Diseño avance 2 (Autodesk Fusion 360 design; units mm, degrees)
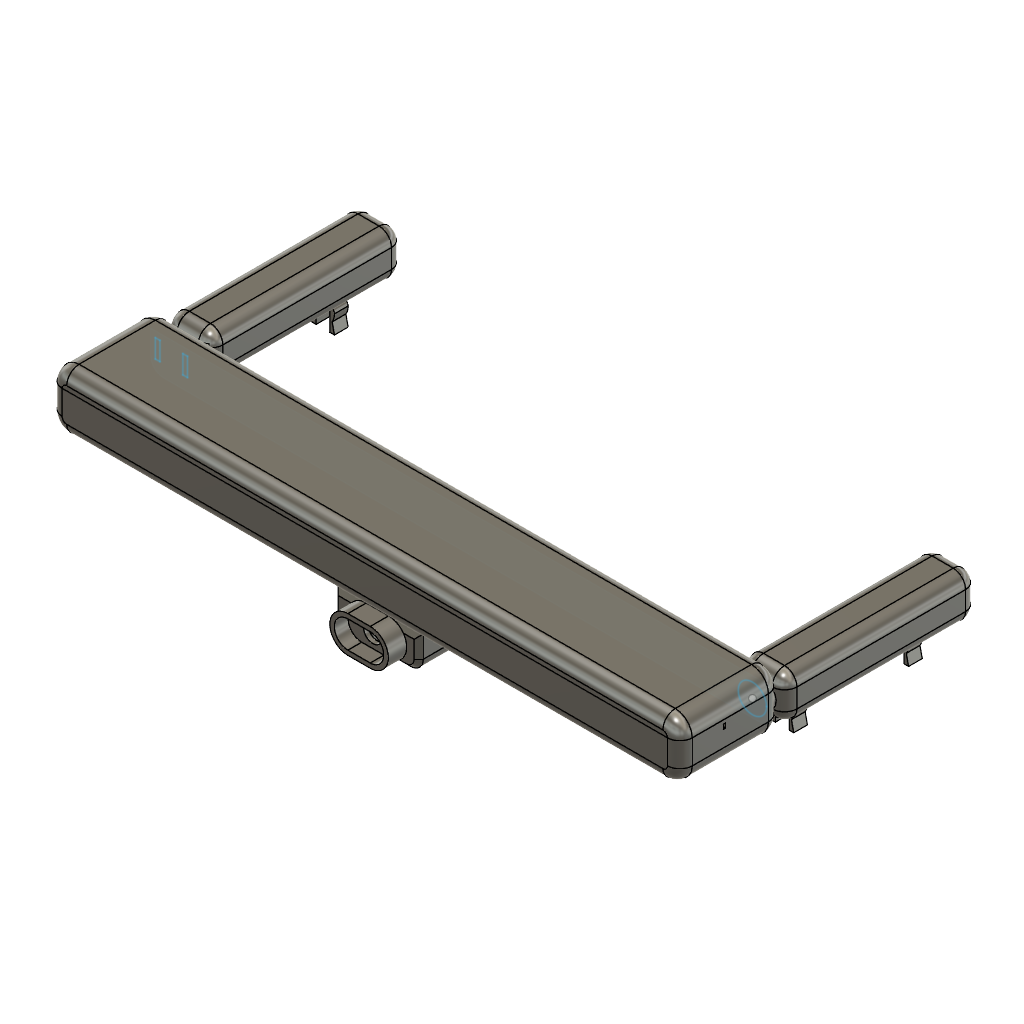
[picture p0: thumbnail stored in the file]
part number: 2026-10-16-14-47-24-830
sketch "Boceto1" plane through (0, 0, 0) normal (0, 0, 1) x axis (1, 0, 0)
  line L1 (42.5013, 50) -> (-87.3, 50)
  line L2 (45.2013, 42.0146) -> (45.2013, 47.3)
  line L3 (-87.3, 39.3146) -> (42.5013, 39.3146)
  line L4 (-90, 47.3) -> (-90, 42.0146)
  arc A1 centre (42.5013, 47.3) radius 2.7 clockwise from (42.5013, 50) to (45.2013, 47.3)
  arc A2 centre (42.5013, 42.0146) radius 2.7 clockwise from (45.2013, 42.0146) to (42.5013, 39.3146)
  arc A3 centre (-87.3, 42.0146) radius 2.7 clockwise from (-87.3, 39.3146) to (-90, 42.0146)
  arc A4 centre (-87.3, 47.3) radius 2.7 clockwise from (-90, 47.3) to (-87.3, 50)
  horizontal L1
  vertical L2
  horizontal L3
  vertical L4
  tangent L1 A1
  tangent L2 A1
  tangent L2 A2
  tangent L3 A2
  equal A1 A2
  tangent L3 A3
  tangent L4 A3
  equal A1 A3
  tangent L1 A4
  tangent L4 A4
  equal A1 A4
  dimension "d4" radius A1 = 2.7
extrude "Extruir1" new body sketch "Boceto1" profile of L1 L2 L3 L4 along normal blind 20
shell "Vaciado1" outerThickness 1
fillet "Empalme1" radius 2.7
fillet "Empalme2" radius 2.7
sketch "Boceto2" plane through (0, 0, 0) normal (1, 0, 0) x axis (0, 0, -1)
  line L1 (30, 47.3179) -> (-39.7648, 47.3179)
  horizontal L1
split "Dividir1"
move "Desplazar1"
sketch "Boceto3" plane through (0, 0, 0) normal (0, 1, 0) x axis (1, 0, 0)
  line L1 (-16.2485, -4.8773) -> (-26.1231, -4.8773)
  line L2 (-13.6485, -12.3188) -> (-13.6485, -7.4773)
  line L3 (-26.1231, -14.9188) -> (-16.2485, -14.9188)
  line L4 (-28.7231, -7.4773) -> (-28.7231, -12.3188)
  arc A1 centre (-16.2485, -7.4773) radius 2.6 clockwise from (-16.2485, -4.8773) to (-13.6485, -7.4773)
  arc A2 centre (-16.2485, -12.3188) radius 2.6 clockwise from (-13.6485, -12.3188) to (-16.2485, -14.9188)
  arc A3 centre (-26.1231, -12.3188) radius 2.6 clockwise from (-26.1231, -14.9188) to (-28.7231, -12.3188)
  arc A4 centre (-26.1231, -7.4773) radius 2.6 clockwise from (-28.7231, -7.4773) to (-26.1231, -4.8773)
  horizontal L1
  vertical L2
  horizontal L3
  vertical L4
  tangent L1 A1
  tangent L2 A1
  tangent L2 A2
  tangent L3 A2
  equal A1 A2
  tangent L3 A3
  tangent L4 A3
  equal A1 A3
  tangent L1 A4
  tangent L4 A4
  equal A1 A4
  dimension "d9" radius A1 = 2.6
extrude "Extruir2" cut sketch "Boceto3" along normal blind 45
sketch "Boceto6" plane through (0, 0, 0) normal (0, 0, 1) x axis (1, 0, 0)
  line L1 (-24.3645, 20) -> (-37.5, 20)
  line L2 (-21.6645, 12.5377) -> (-21.6645, 17.3)
  line L3 (-37.5, 9.8377) -> (-24.3645, 9.8377)
  line L4 (-40.2, 17.3) -> (-40.2, 12.5377)
  arc A1 centre (-24.3645, 17.3) radius 2.7 clockwise from (-24.3645, 20) to (-21.6645, 17.3)
  arc A2 centre (-24.3645, 12.5377) radius 2.7 clockwise from (-21.6645, 12.5377) to (-24.3645, 9.8377)
  arc A3 centre (-37.5, 12.5377) radius 2.7 clockwise from (-37.5, 9.8377) to (-40.2, 12.5377)
  arc A4 centre (-37.5, 17.3) radius 2.7 clockwise from (-40.2, 17.3) to (-37.5, 20)
  horizontal L1
  vertical L2
  horizontal L3
  vertical L4
  tangent L1 A1
  tangent L2 A1
  tangent L2 A2
  tangent L3 A2
  equal A1 A2
  tangent L3 A3
  tangent L4 A3
  equal A1 A3
  tangent L1 A4
  tangent L4 A4
  equal A1 A4
  dimension "d22" radius A1 = 2.7
extrude "Extruir5" new body sketch "Boceto6" profile of L1 L2 L3 L4 along normal blind 20
move "Desplazar6"
move "Desplazar7"
move "Desplazar8"
shell "Vaciado2" innerThickness 1
move "Desplazar9"
sketch "Boceto8" plane through (0, 0, 140) normal (0, 0, 1) x axis (1, 0, 0)
  line L1 (-5.2925, 37.3) -> (-33.9746, 37.3)
  line L2 (-27.5, 40) -> (-14.3645, 40)
  line L3 (-30.2, 32.5377) -> (-30.2, 37.3)
  line L4 (-14.3645, 29.8377) -> (-27.5, 29.8377)
  line L5 (-11.6645, 37.3) -> (-11.6645, 32.5377)
  arc A1 centre (-14.3645, 37.3) radius 2.7 clockwise from (-14.3645, 40) to (-11.6645, 37.3)
  arc A2 centre (-27.5, 37.3) radius 2.7 clockwise from (-30.2, 37.3) to (-27.5, 40)
  arc A3 centre (-27.5, 32.5377) radius 2.7 clockwise from (-27.5, 29.8377) to (-30.2, 32.5377)
  arc A4 centre (-14.3645, 32.5377) radius 2.7 clockwise from (-11.6645, 32.5377) to (-14.3645, 29.8377)
split "Dividir2"
move "Desplazar10"
move "Desplazar11"
move "Desplazar12"
remove_body "QuitarCuerpo"
move "Desplazar13"
hole "Agujero1" HoleDepth 1 HoleDiameter 2 TipAngle 180
hole "Agujero2" HoleDepth 1 HoleDiameter 2 TipAngle 180
hole "Agujero3" HoleDepth 1 HoleDiameter 2 TipAngle 180
chamfer "Chaflán1" distance 1
chamfer "Chaflán2" distance 1
sketch "Boceto10" plane through (0, 0, 0) normal (0, 0, 1) x axis (1, 0, 0)
  line L1 (-34.2158, 4.9543) -> (-39.0711, 4.9543)
  line L2 (-39.0711, -2.9416) -> (-34.2158, -2.9416)
  arc A1 centre (-34.2158, 1.0063) radius 3.948 clockwise from (-34.2158, 4.9543) to (-34.2158, -2.9416)
  arc A2 centre (-39.0711, 1.0063) radius 3.948 clockwise from (-39.0711, -2.9416) to (-39.0711, 4.9543)
  horizontal L1
  tangent L1 A1
  tangent A1 L2
  parallel L1 L2
  tangent L1 A2
  tangent L2 A2
extrude "Extruir6" new body sketch "Boceto10" along normal blind 4
move "Desplazar14"
shell "Vaciado3" innerThickness 1
hole "Agujero4" HoleDepth 1 HoleDiameter 4 TipAngle 180
move "Desplazar15"
move "Desplazar16"
move "Desplazar17"
sketch "Boceto11" plane through (0, 0, 0) normal (1, 0, 0) x axis (0, 0, -1)
  line L1 (49.4173, 10) -> (12.7, 10)
  line L2 (52.1173, 3.1558) -> (52.1173, 7.3)
  line L3 (12.7, 0.4558) -> (49.4173, 0.4558)
  line L4 (10, 7.3) -> (10, 3.1558)
  arc A1 centre (49.4173, 7.3) radius 2.7 clockwise from (49.4173, 10) to (52.1173, 7.3)
  arc A2 centre (49.4173, 3.1558) radius 2.7 clockwise from (52.1173, 3.1558) to (49.4173, 0.4558)
  arc A3 centre (12.7, 3.1558) radius 2.7 clockwise from (12.7, 0.4558) to (10, 3.1558)
  arc A4 centre (12.7, 7.3) radius 2.7 clockwise from (10, 7.3) to (12.7, 10)
  horizontal L1
  vertical L2
  horizontal L3
  vertical L4
  tangent L1 A1
  tangent L2 A1
  tangent L2 A2
  tangent L3 A2
  equal A1 A2
  tangent L3 A3
  tangent L4 A3
  equal A1 A3
  tangent L1 A4
  tangent L4 A4
  equal A1 A4
  dimension "d47" radius A1 = 2.7
extrude "Extruir7" new body sketch "Boceto11" profile of L1 L2 L3 L4 along normal blind 10
move "Desplazar18"
copy_paste_bodies "CopiarPegarCuerpos1"
move "Desplazar19"
fillet "Empalme5" radius 2.7
fillet "Empalme6" radius 2.7
sketch "Boceto13" plane through (0, 10, 0) normal (0, 1, 0) x axis (-1, 0, 0)
  line L1 (-2.7, -72.7) -> (-2.7, -109.4173)
  line L2 (-7.3, -72.7) -> (-2.7, -72.7)
  line L3 (-7.3, -109.4173) -> (-7.3, -72.7)
  line L4 (-2.7, -109.4173) -> (-7.3, -109.4173)
  line L5 (-2.7, -115.7309) -> (-2.7211, -64.7601)
split "Dividir3"
move "Desplazar20"
shell "Vaciado4" innerThickness 1
move "Desplazar21"
shell "Vaciado5" innerThickness 1
sketch "Boceto15" plane through (-16, 0, 0) normal (-1, 0, 0) x axis (0, 0, 1)
  line L1 (-109.4173, 3.1558) -> (-109.4173, 7.3)
  line L2 (-72.7, 3.1558) -> (-109.4173, 3.1558)
  line L3 (-72.7, 7.3) -> (-72.7, 3.1558)
  line L4 (-109.4173, 7.3) -> (-72.7, 7.3)
  line L5 (-104, 7) -> (-105, 7)
  line L6 (-104, 4) -> (-104, 7)
  line L7 (-105, 4) -> (-104, 4)
  line L8 (-105, 7) -> (-105, 4)
  horizontal L5
  vertical L6
  horizontal L7
  vertical L8
extrude "Extruir8" cut sketch "Boceto15" profile of L5 L6 L7 L8 distance 2
sketch "Boceto16" plane through (-16, 0, 0) normal (-1, 0, 0) x axis (0, 0, 1)
  line L1 (-105, 7) -> (-105, 4)
  line L2 (-104, 7) -> (-105, 7)
  line L3 (-104, 4) -> (-104, 7)
  line L4 (-105, 4) -> (-104, 4)
  line L5 (-109.4173, 3.1558) -> (-109.4173, 7.3)
  line L6 (-72.7, 3.1558) -> (-109.4173, 3.1558)
  line L7 (-72.7, 7.3) -> (-72.7, 3.1558)
  line L8 (-109.4173, 7.3) -> (-72.7, 7.3)
  line L9 (-106, 7) -> (-107, 7)
  line L10 (-106, 4) -> (-106, 7)
  line L11 (-107, 4) -> (-106, 4)
  line L12 (-107, 7) -> (-107, 4)
  horizontal L9
  vertical L10
  horizontal L11
  vertical L12
extrude "Extruir9" cut sketch "Boceto16" profile of L9 L10 L11 L12 distance 2
sketch "Boceto17" plane through (-16, 0, 0) normal (-1, 0, 0) x axis (0, 0, 1)
  line L1 (-107, 7) -> (-107, 4)
  line L2 (-106, 7) -> (-107, 7)
  line L3 (-106, 4) -> (-106, 7)
  line L4 (-107, 4) -> (-106, 4)
  line L5 (-105, 7) -> (-105, 4)
  line L6 (-104, 7) -> (-105, 7)
  line L7 (-104, 4) -> (-104, 7)
  line L8 (-105, 4) -> (-104, 4)
  line L9 (-109.4173, 3.1558) -> (-109.4173, 7.3)
  line L10 (-72.7, 3.1558) -> (-109.4173, 3.1558)
  line L11 (-72.7, 7.3) -> (-72.7, 3.1558)
  line L12 (-109.4173, 7.3) -> (-72.7, 7.3)
  line L13 (-102, 7) -> (-103, 7)
  line L14 (-102, 4) -> (-102, 7)
  line L15 (-103, 4) -> (-102, 4)
  line L16 (-103, 7) -> (-103, 4)
  horizontal L13
  vertical L14
  horizontal L15
  vertical L16
extrude "Extruir10" cut sketch "Boceto17" profile of L13 L14 L15 L16 distance 3
sketch "Boceto18" plane through (-16, 0, 0) normal (-1, 0, 0) x axis (0, 0, 1)
  line L1 (-103, 7) -> (-103, 4)
  line L2 (-102, 7) -> (-103, 7)
  line L3 (-102, 4) -> (-102, 7)
  line L4 (-103, 4) -> (-102, 4)
  line L5 (-107, 7) -> (-107, 4)
  line L6 (-106, 7) -> (-107, 7)
  line L7 (-106, 4) -> (-106, 7)
  line L8 (-107, 4) -> (-106, 4)
  line L9 (-105, 7) -> (-105, 4)
  line L10 (-104, 7) -> (-105, 7)
  line L11 (-104, 4) -> (-104, 7)
  line L12 (-105, 4) -> (-104, 4)
  line L13 (-109.4173, 3.1558) -> (-109.4173, 7.3)
  line L14 (-72.7, 3.1558) -> (-109.4173, 3.1558)
  line L15 (-72.7, 7.3) -> (-72.7, 3.1558)
  line L16 (-109.4173, 7.3) -> (-72.7, 7.3)
  line L17 (-100, 7) -> (-101, 7)
  line L18 (-100, 4) -> (-100, 7)
  line L19 (-101, 4) -> (-100, 4)
  line L20 (-101, 7) -> (-101, 4)
  horizontal L17
  vertical L18
  horizontal L19
  vertical L20
extrude "Extruir11" cut sketch "Boceto18" profile of L17 L18 L19 L20 distance 5
move "Desplazar22"
move "Desplazar23"
move "Desplazar24"
move "Desplazar25"
move "Desplazar26"
move "Desplazar27"
move "Desplazar28"
move "Desplazar29"
move "Desplazar30"
move "Desplazar31"
move "Desplazar32"
move "Desplazar33"
move "Desplazar34"
fillet "Empalme7" radius 2.7
fillet "Empalme8" radius 2.7
move "Desplazar35"
move "Desplazar36"
move "Desplazar37"
sketch "Boceto21" plane through (0, 0, 0) normal (0, 0, 1) x axis (1, 0, 0)
  line L1 (53.1892, 36.5432) -> (53.1892, 51.0031)
  vertical L1
move "Desplazar40"
move "Desplazar41"
move "Desplazar46"
move "Desplazar47"
move "Desplazar48"
move "Desplazar49"
sketch "Boceto24" plane through (46.2013, 0, 0) normal (1, 0, 0) x axis (0, 0, -1)
  line L1 (-1.7, 47.3) -> (-1.7, 42.0146)
  line L2 (-18.3, 47.3) -> (-1.7, 47.3)
  line L3 (-18.3, 42.0146) -> (-18.3, 47.3)
  line L4 (-1.7, 42.0146) -> (-18.3, 42.0146)
  line L5 (-11, 46.5) -> (-11.5, 46.5)
  line L6 (-11, 45.5) -> (-11, 46.5)
  line L7 (-11.5, 45.5) -> (-11, 45.5)
  line L8 (-11.5, 46.5) -> (-11.5, 45.5)
  horizontal L5
  vertical L6
  horizontal L7
  vertical L8
extrude "Extruir16" cut sketch "Boceto24" profile of L5 L6 L7 L8 distance 1
sketch "Boceto25" plane through (-91, 0, 0) normal (-1, 0, 0) x axis (0, 0, 1)
  line L1 (1.7, 42.0146) -> (1.7, 47.3)
  line L2 (18.3, 42.0146) -> (1.7, 42.0146)
  line L3 (18.3, 47.3) -> (18.3, 42.0146)
  line L4 (1.7, 47.3) -> (18.3, 47.3)
  line L5 (9.4955, 42.5) -> (8, 42.5)
  line L6 (9.4955, 42.0146) -> (9.4955, 42.5)
  line L7 (8, 42.0146) -> (9.4955, 42.0146)
  line L8 (8, 42.5) -> (8, 42.0146)
  point P8 (9.4955, 42.0146)
  horizontal L5
  vertical L6
  horizontal L7
  vertical L8
  coincident L2 P8
extrude "Extruir17" cut sketch "Boceto25" profile of L2 L5 L6 L7 L8 distance 4.5
move "Desplazar50"
move "Desplazar51"
sketch "Boceto27" plane through (0, 0, 0) normal (0, 0, 1) x axis (1, 0, 0)
  line L1 (-89.9999, 47.3179) -> (45.2013, 47.3179)
  line L2 (-90, 42.0146) -> (-90, 47.3)
  line L3 (42.5013, 39.3146) -> (-87.3, 39.3146)
  line L4 (45.2013, 47.3) -> (45.2013, 42.0146)
  line L5 (-88, 46) -> (-89, 46)
  line L6 (-88, 42) -> (-88, 46)
  line L7 (-89, 42) -> (-88, 42)
  line L8 (-89, 46) -> (-89, 42)
  arc A1 centre (-87.3, 47.3) radius 2.7 clockwise from (-90, 47.3) to (-89.9999, 47.3179)
  arc A2 centre (-87.3, 42.0146) radius 2.7 clockwise from (-87.3, 39.3146) to (-90, 42.0146)
  arc A3 centre (42.5013, 42.0146) radius 2.7 clockwise from (45.2013, 42.0146) to (42.5013, 39.3146)
  arc A4 centre (42.5013, 47.3) radius 2.7 clockwise from (45.2013, 47.3179) to (45.2013, 47.3)
  horizontal L5
  vertical L6
  horizontal L7
  vertical L8
extrude "Extruir20" cut sketch "Boceto27" profile of L5 L6 L7 L8 along normal blind 2 and against normal blind 7
extrude "Extruir21" add sketch "Boceto27" profile of L5 L6 L7 L8 along normal blind 0 and against normal blind 3
sketch "Boceto28" plane through (0, 0, 0) normal (0, 0, 1) x axis (1, 0, 0)
  line L1 (-82, 46) -> (-83, 46)
  line L2 (-82, 42) -> (-82, 46)
  line L3 (-83, 42) -> (-82, 42)
  line L4 (-83, 46) -> (-83, 42)
  horizontal L1
  vertical L2
  horizontal L3
  vertical L4
extrude "Extruir22" cut sketch "Boceto28" along normal blind 0 and against normal blind 8
extrude "Extruir23" add sketch "Boceto28" along normal blind 0 and against normal blind 3
sketch "Boceto29" plane through (0, 0, 0) normal (0, 0, 1) x axis (1, 0, 0)
  line L1 (-84, 46) -> (-87, 46)
  line L2 (-84, 42) -> (-84, 46)
  line L3 (-87, 42) -> (-84, 42)
  line L4 (-87, 46) -> (-87, 42)
  horizontal L1
  vertical L2
  horizontal L3
  vertical L4
extrude "Extruir24" cut sketch "Boceto29" along normal blind 0 and against normal blind 7
move "Desplazar61"
move "Desplazar62"
move "Desplazar63"
move "Desplazar64"
sketch "Boceto33" plane through (0, 0, 0) normal (0, 0, 1) x axis (1, 0, 0)
  circle C1 centre (41, 43) radius 3.0754
extrude "Extruir26" cut sketch "Boceto33" along normal blind 0 and against normal blind 6
extrude "Extruir27" add sketch "Boceto33" along normal blind 0 and against normal blind 3
move "Desplazar65"
sketch "Boceto35" plane through (0, 0, 0) normal (0, 0, 1) x axis (1, 0, 0)
sketch "Boceto36" plane through (0, 0, 0) normal (0, 0, 1) x axis (1, 0, 0)
  line L1 (18.9993, 4.9982) -> (15.8905, 4.9982)
  line L2 (14.8905, 4) -> (20, 4)
  line L3 (20, 4) -> (19, 4)
  line L4 (19, 0) -> (20, 0)
  line L5 (19, 4) -> (19, 0)
  line L6 (16, 4) -> (14.8905, 4)
  line L7 (16, 0) -> (16, 4)
  line L8 (14.9075, 0) -> (16, 0)
  line L9 (20, 0) -> (19.5, 2.246)
  line L10 (14.9075, 0) -> (15.3927, 2.2339)
  arc A1 centre (18.9993, 3.9982) radius 1 clockwise from (18.9993, 4.9982) to (19.9993, 3.9979)
  arc A2 centre (15.8905, 3.9982) radius 1 clockwise from (14.8905, 4) to (15.8905, 4.9982)
  arc A3 centre (18.2258, 3.9939) radius 3.3353 clockwise from (15.3927, 2.2339) to (14.8905, 4)
  arc A4 centre (16.6728, 3.9988) radius 3.3265 clockwise from (19.9993, 3.9979) to (19.5, 2.246)
  point P4 (19, 4)
  point P3 (14.8905, 4)
  point P15 (14.8905, 4)
  horizontal L1
  horizontal L2
  horizontal L3
  horizontal L4
  vertical L5
  coincident L2 P4
  horizontal L6
  vertical L7
  horizontal L8
  tangent L1 A1
  tangent L1 A2
  equal A1 A2
  coincident P3 P15
  tangent A2 A3
  tangent A1 A4
  dimension "d119" radius A1 = 1
extrude "Extruir29" new body sketch "Boceto36" along normal blind 3
move "Desplazar67"
copy_paste_bodies "CopiarPegarCuerpos2"
move "Desplazar68"
copy_paste_bodies "CopiarPegarCuerpos3"
move "Desplazar69"
copy_paste_bodies "CopiarPegarCuerpos4"
move "Desplazar70"
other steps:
base_feature "Elemento base1"
base_feature "Elemento base2"
base_feature "Elemento base3"
base_feature "Elemento base4"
